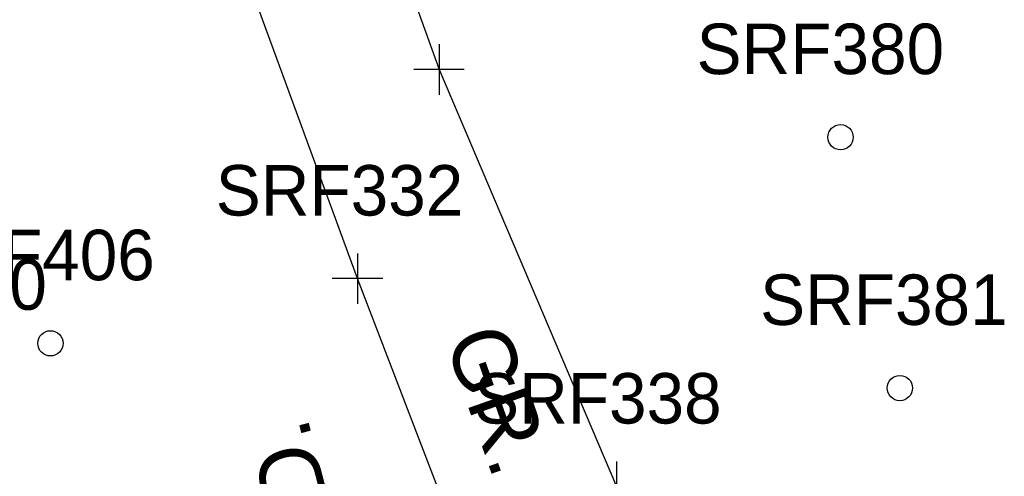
# Model space of a CAD drawing. Extents: x 818717 to 846077, y 440014 to 541392.
# Drawn here: x 832182.9 to 832261, y 493300 to 493336.2 of the extents above; entities that cross this region are included whole.
import ezdxf

# ---------------------------------------------------------------- set-up
doc = ezdxf.new("R2010")
doc.units = 0
for name, color, linetype in [('SURVEY - DTM - Spot Points - Locators', 7, 'Continuous'), ('SURVEY - DTM - Spot Points - Point Numbers', 7, 'Continuous'), ('SURVEY - TRANSPORTATION - Features', 7, 'Continuous'), ('SURVEY - TRANSPORTATION - Features - Points - Locators', 7, 'Continuous'), ('SURVEY - TRANSPORTATION - Features - Points - Numbers', 7, 'Continuous'), ('SURVEY - TRANSPORTATION - Features Text', 7, 'Continuous'), ('SURVEY - UTILITIES - Telephone (Underground) with Text', 7, 'Continuous')]:
    doc.layers.add(name, color=color, linetype=linetype)

msp = doc.modelspace()

# ---------------------------------------------------------------- linework, layer by layer
at = {"layer": 'SURVEY - DTM - Spot Points - Locators'}
for centre in [(832247.994, 493326.888), (832185.36, 493310.559), (832252.697, 493307.014)]:
    msp.add_circle(centre, 1, dxfattribs=at)
at = {"layer": 'SURVEY - TRANSPORTATION - Features'}
for points in [[(832196.53, 493391.096), (832204.746, 493363.999), (832216.164, 493332.256), (832230.23, 493299.202), (832241.299, 493272.281), (832244.196, 493265.688), (832251.053, 493261.066)], [(832223.175, 493253.672), (832226.488, 493262.952), (832226.397, 493267.012), (832226.483, 493271.976), (832209.702, 493315.682), (832193.964, 493358.654), (832185.251, 493388.054)]]:
    msp.add_lwpolyline(points, dxfattribs=at)
at = {"layer": 'SURVEY - TRANSPORTATION - Features - Points - Locators'}
for p, q in [((832216.164, 493334.256), (832216.164, 493330.256)), ((832218.164, 493332.256), (832214.164, 493332.256)), ((832209.702, 493317.682), (832209.702, 493313.682)), ((832211.702, 493315.682), (832207.702, 493315.682)), ((832230.23, 493301.202), (832230.23, 493297.202))]:
    msp.add_line(p, q, dxfattribs=at)

# ---------------------------------------------------------------- texts
at = {"layer": 'SURVEY - DTM - Spot Points - Point Numbers'}
for s, p in [('SRF380', (832236.581, 493331.888)), ('SRF406', (832174.01, 493315.559)), ('SRF440', (832165.458, 493313.216)), ('SRF381', (832241.615, 493312.014))]:
    msp.add_text(s, height=4, dxfattribs=at).set_placement(p)
at = {"layer": 'SURVEY - TRANSPORTATION - Features - Points - Numbers'}
for s, p in [('SRF332', (832198.462, 493320.682)), ('SRF338', (832218.943, 493304.202))]:
    msp.add_text(s, height=4, dxfattribs=at).set_placement(p)
at = {"layer": 'SURVEY - TRANSPORTATION - Features Text'}
msp.add_text('GR. DR.', height=5, rotation=289.36429, dxfattribs=at).set_placement((832216.589, 493310.862))
at = {"layer": 'SURVEY - UTILITIES - Telephone (Underground) with Text'}
msp.add_text('TEL. PED.', height=5.0001, rotation=104.6355, dxfattribs=at).set_placement((832213.663, 493274.289))

doc.saveas('drawing.dxf')
